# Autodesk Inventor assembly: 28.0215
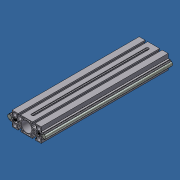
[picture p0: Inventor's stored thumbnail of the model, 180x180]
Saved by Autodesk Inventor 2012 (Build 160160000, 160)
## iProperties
Created: 2011-05
Part Number: 28.0215
Document SubType Name: Assembly
Designer: Administrator
Description: Rail 45x90 F For ADJ UNITS
Author: Administrator
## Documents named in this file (4)
- C:\Andys Backup Data\ANDY'S INVENTOR\INVENTOR LIBRARIES\PARTS LIBRARY\READY FOR USE MODULES LG\SUBCOMPONENTS\28.0215 RAIL 45X90F.iam
- C:\Andys Backup Data\ANDY'S INVENTOR\INVENTOR LIBRARIES\PARTS LIBRARY\READY FOR USE MODULES LG\SUBCOMPONENTS\28.0215_1.ipt
- C:\Andys Backup Data\ANDY'S INVENTOR\INVENTOR LIBRARIES\PARTS LIBRARY\READY FOR USE MODULES LG\SUBCOMPONENTS\28.0215_8 SHAFT 12.ipt
- C:\Andys Backup Data\ANDY'S INVENTOR\INVENTOR LIBRARIES\PARTS LIBRARY\READY FOR USE MODULES LG\SUBCOMPONENTS\28.0215_9 SHAFT SUPP PROF.ipt
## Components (5 placed, 3 different names)
1. 28.0215_1:1 — Mate:3, Mate:4, Mate:5, Mate:6, Mate:7, Mate:8
2. 28.0215_8 SHAFT 12:1 — Mate:2, Flush:3, Mate:4
3. 28.0215_8 SHAFT 12:2 — Mate:1, Flush:2, Mate:6
4. 28.0215_9 SHAFT SUPP PROF:1 — Mate:1, Flush:2, Mate:5, Mate:7
5. 28.0215_9 SHAFT SUPP PROF:2 — Mate:2, Flush:3, Mate:3, Mate:8
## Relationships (10: Mate 8, Flush 2)
- Mate:1: 28.0215_8 SHAFT 12:2 ↔ 28.0215_9 SHAFT SUPP PROF:1
- Flush:2: 28.0215_8 SHAFT 12:2 ↔ 28.0215_9 SHAFT SUPP PROF:1
- Mate:2: 28.0215_8 SHAFT 12:1 ↔ 28.0215_9 SHAFT SUPP PROF:2
- Flush:3: 28.0215_8 SHAFT 12:1 ↔ 28.0215_9 SHAFT SUPP PROF:2
- Mate:3: 28.0215_1:1 ↔ 28.0215_9 SHAFT SUPP PROF:2
- Mate:4: 28.0215_1:1 ↔ 28.0215_8 SHAFT 12:1
- Mate:5: 28.0215_1:1 ↔ 28.0215_9 SHAFT SUPP PROF:1
- Mate:6: 28.0215_1:1 ↔ 28.0215_8 SHAFT 12:2
- Mate:7: 28.0215_1:1 ↔ 28.0215_9 SHAFT SUPP PROF:1
- Mate:8: 28.0215_1:1 ↔ 28.0215_9 SHAFT SUPP PROF:2
